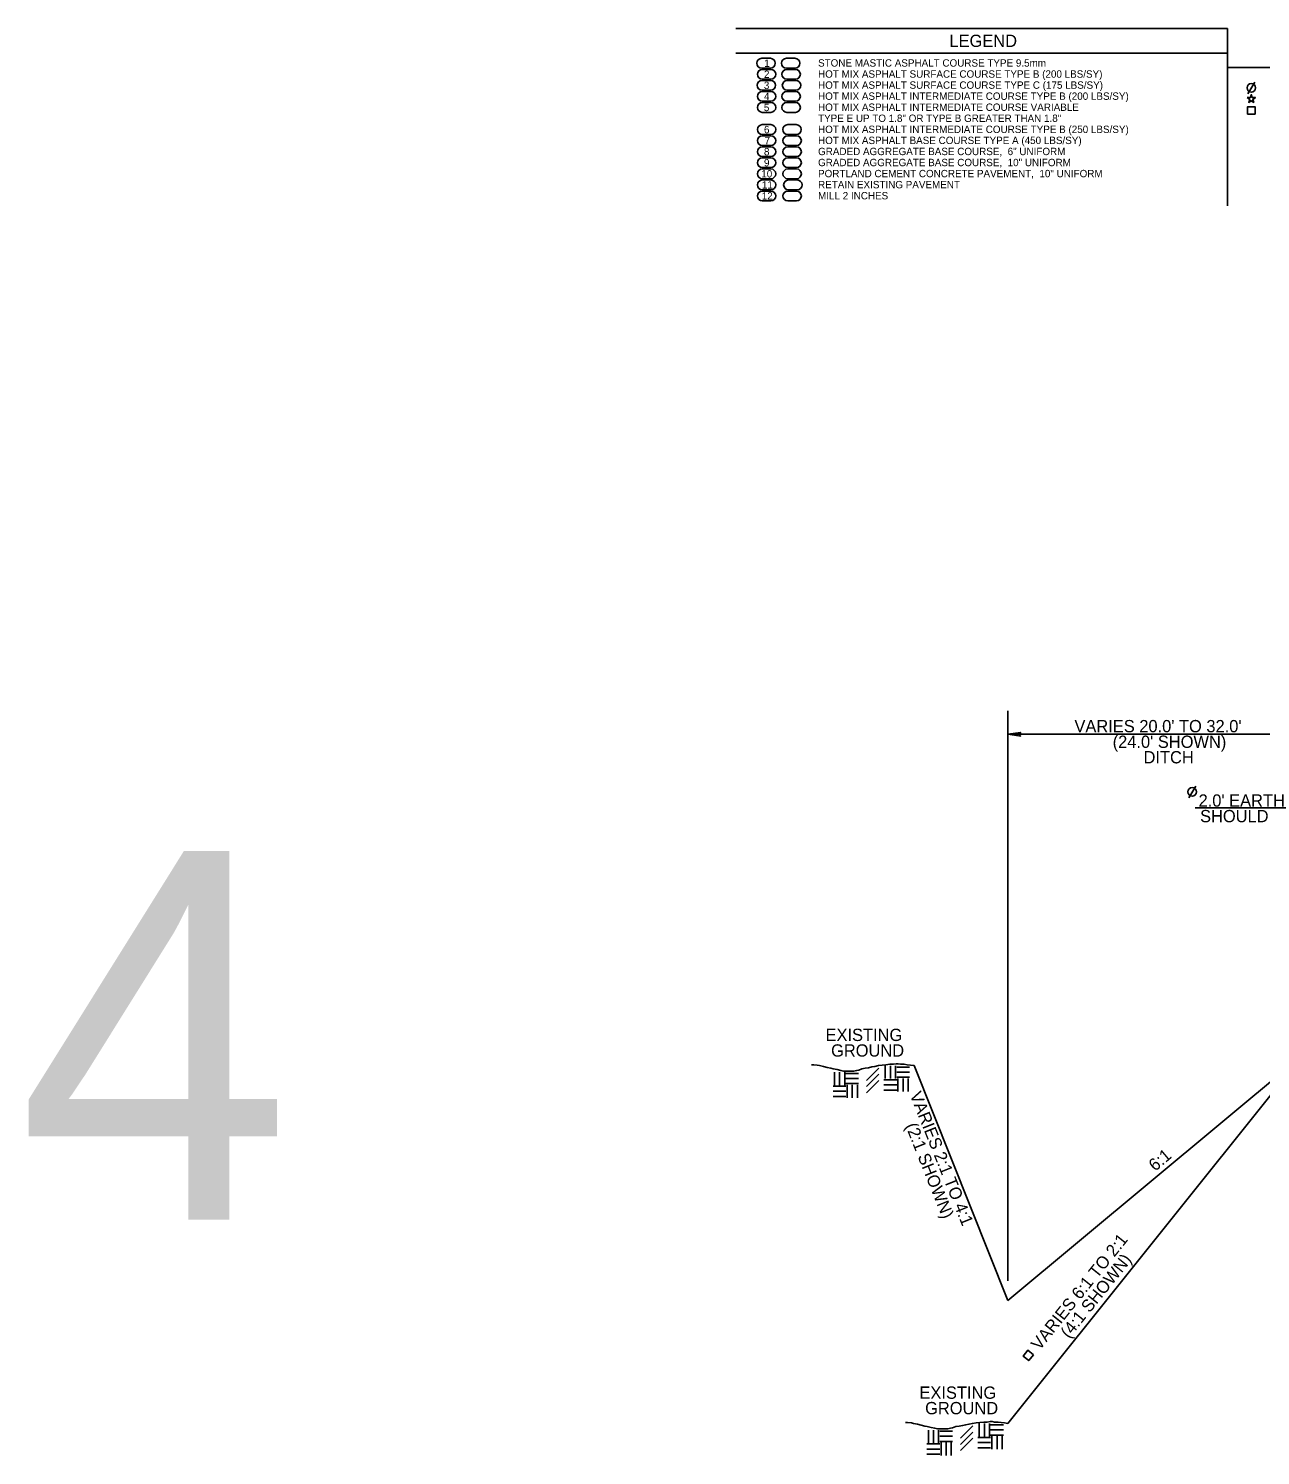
# Model space of a CAD drawing. Extents: x 2003207 to 2014043, y 843846 to 860154.
# Drawn here: x 2013558.2 to 2013658.4, y 844584.3 to 844700.4 of the extents above; entities that cross this region are included whole.
import ezdxf

# ---------------------------------------------------------------- set-up
doc = ezdxf.new("R2010")
doc.units = 0
for name, color, linetype in [('RD_EX_Road', 7, 'Continuous'), ('RD_EX_Road_txCode', 7, 'Continuous'), ('RD_QTY_ConcPave', 7, 'Continuous'), ('RD_QTY_Intermediate', 7, 'Continuous'), ('RD_QTY_Milling', 7, 'Continuous'), ('RD_QTY_PermVeg', 7, 'Continuous'), ('RD_QTY_Surf_Course', 7, 'Continuous'), ('RD_SHT_Bndy', 7, 'Continuous'), ('RD_SHT_TX', 7, 'Continuous'), ('RD_TX_Misc2', 7, 'Continuous'), ('RD_TX_TypSect', 7, 'Continuous'), ('RD_XS_ExGround', 7, 'Continuous')]:
    doc.layers.add(name, color=color, linetype=linetype)

msp = doc.modelspace()

# ---------------------------------------------------------------- linework, layer by layer
at = {"layer": 'RD_EX_Road'}
for p, q in [((2013620.66, 844687.19), (2013619.96, 844687.19)), ((2013620.72, 844688.09), (2013620.02, 844688.09)), ((2013620.02, 844687.29), (2013620.72, 844687.29)), ((2013619.96, 844686.39), (2013620.66, 844686.39))]:
    msp.add_line(p, q, dxfattribs=at)
for centre, start, end in [((2013619.96, 844686.79), 90, 270), ((2013620.02, 844687.69), 90, 270), ((2013620.66, 844686.79), 270, 90), ((2013620.72, 844687.69), 270, 90)]:
    msp.add_arc(centre, 0.4, start, end, dxfattribs=at)
at = {"layer": 'RD_EX_Road_txCode'}
msp.add_line((2013657.38, 844695.11), (2013657.95, 844696.05), dxfattribs=at)
for points in [[(2013657.33, 844694.79), (2013657.59, 844694.79), (2013657.67, 844695.03), (2013657.75, 844694.79), (2013658, 844694.79), (2013657.79, 844694.64), (2013657.87, 844694.4), (2013657.67, 844694.54), (2013657.46, 844694.4), (2013657.54, 844694.64)], [(2013657.37, 844693.45), (2013657.97, 844693.45), (2013657.97, 844694.05), (2013657.37, 844694.05)], [(2013639.94, 844592.49), (2013639.56, 844592.03), (2013639.1, 844592.4), (2013639.48, 844592.87)]]:
    msp.add_lwpolyline(points, close=True, dxfattribs=at)
msp.add_circle((2013657.67, 844695.58), 0.35, dxfattribs=at)
at = {"layer": 'RD_QTY_ConcPave'}
for p, q in [((2013620.66, 844690.79), (2013619.96, 844690.79)), ((2013619.96, 844689.99), (2013620.66, 844689.99)), ((2013620.66, 844689.89), (2013619.96, 844689.89)), ((2013619.96, 844689.09), (2013620.66, 844689.09)), ((2013620.66, 844688.99), (2013619.96, 844688.99)), ((2013619.96, 844688.19), (2013620.66, 844688.19))]:
    msp.add_line(p, q, dxfattribs=at)
for centre, start, end in [((2013619.96, 844690.39), 90, 270), ((2013620.66, 844690.39), 270, 90), ((2013619.96, 844689.49), 90, 270), ((2013620.66, 844689.49), 270, 90), ((2013619.96, 844688.59), 90, 270), ((2013620.66, 844688.59), 270, 90)]:
    msp.add_arc(centre, 0.4, start, end, dxfattribs=at)
at = {"layer": 'RD_QTY_Intermediate'}
for p, q in [((2013620.58, 844695.29), (2013619.88, 844695.29)), ((2013619.88, 844694.49), (2013620.58, 844694.49)), ((2013620.58, 844694.39), (2013619.88, 844694.39)), ((2013619.88, 844693.59), (2013620.58, 844693.59)), ((2013620.65, 844692.59), (2013619.95, 844692.59)), ((2013619.95, 844691.79), (2013620.65, 844691.79)), ((2013620.66, 844691.69), (2013619.96, 844691.69)), ((2013619.96, 844690.89), (2013620.66, 844690.89))]:
    msp.add_line(p, q, dxfattribs=at)
for centre, start, end in [((2013619.88, 844694.89), 90, 270), ((2013620.58, 844694.89), 270, 90), ((2013619.88, 844693.99), 90, 270), ((2013620.58, 844693.99), 270, 90), ((2013619.95, 844692.19), 90, 270), ((2013619.96, 844691.29), 90, 270), ((2013620.65, 844692.19), 270, 90), ((2013620.66, 844691.29), 270, 90)]:
    msp.add_arc(centre, 0.4, start, end, dxfattribs=at)
at = {"layer": 'RD_QTY_Milling'}
for p, q in [((2013620.66, 844687.19), (2013619.96, 844687.19)), ((2013619.96, 844686.39), (2013620.66, 844686.39))]:
    msp.add_line(p, q, dxfattribs=at)
for centre, start, end in [((2013619.96, 844686.79), 90, 270), ((2013620.66, 844686.79), 270, 90)]:
    msp.add_arc(centre, 0.4, start, end, dxfattribs=at)
at = {"layer": 'RD_QTY_PermVeg'}
for p, q in [((2013661.87, 844616.92), (2013637.87, 844596.92)), ((2013661.87, 844616.92), (2013637.87, 844586.92)), ((2013637.87, 844596.92), (2013630.23, 844616.03))]:
    msp.add_line(p, q, dxfattribs=at)
at = {"layer": 'RD_QTY_Surf_Course'}
for p, q in [((2013620.54, 844697.99), (2013619.84, 844697.99)), ((2013619.84, 844697.19), (2013620.54, 844697.19)), ((2013620.58, 844697.09), (2013619.88, 844697.09)), ((2013619.88, 844696.29), (2013620.58, 844696.29)), ((2013620.61, 844696.19), (2013619.91, 844696.19)), ((2013619.91, 844695.39), (2013620.61, 844695.39))]:
    msp.add_line(p, q, dxfattribs=at)
for centre, start, end in [((2013619.84, 844697.59), 90, 270), ((2013620.54, 844697.59), 270, 90), ((2013619.88, 844696.69), 90, 270), ((2013620.58, 844696.69), 270, 90), ((2013619.91, 844695.79), 90, 270), ((2013620.61, 844695.79), 270, 90)]:
    msp.add_arc(centre, 0.4, start, end, dxfattribs=at)
at = {"layer": 'RD_SHT_Bndy'}
for p, q in [((2013655.72, 844700.41), (2013615.72, 844700.41)), ((2013655.72, 844698.41), (2013655.72, 844700.41)), ((2013655.72, 844698.41), (2013615.72, 844698.41)), ((2013655.72, 844685.99), (2013655.72, 844698.41)), ((2013678.75, 844697.24), (2013655.75, 844697.24))]:
    msp.add_line(p, q, dxfattribs=at)
at = {"layer": 'RD_TX_Misc2'}
for p, q in [((2013617.84, 844697.99), (2013618.54, 844697.99)), ((2013619.84, 844697.99), (2013620.54, 844697.99)), ((2013617.84, 844697.19), (2013618.54, 844697.19)), ((2013617.88, 844697.09), (2013618.58, 844697.09)), ((2013617.88, 844696.29), (2013618.58, 844696.29)), ((2013619.84, 844697.19), (2013620.54, 844697.19)), ((2013619.88, 844697.09), (2013620.58, 844697.09)), ((2013619.88, 844696.29), (2013620.58, 844696.29)), ((2013617.87, 844696.19), (2013618.57, 844696.19)), ((2013617.87, 844695.39), (2013618.57, 844695.39)), ((2013617.88, 844695.29), (2013618.58, 844695.29)), ((2013619.88, 844695.29), (2013620.58, 844695.29)), ((2013619.91, 844696.19), (2013620.61, 844696.19)), ((2013619.91, 844695.39), (2013620.61, 844695.39)), ((2013617.88, 844694.49), (2013618.58, 844694.49)), ((2013617.88, 844694.39), (2013618.58, 844694.39)), ((2013619.88, 844694.49), (2013620.58, 844694.49)), ((2013619.88, 844694.39), (2013620.58, 844694.39)), ((2013617.88, 844693.59), (2013618.58, 844693.59)), ((2013619.88, 844693.59), (2013620.58, 844693.59)), ((2013617.88, 844692.59), (2013618.58, 844692.59)), ((2013617.88, 844691.79), (2013618.58, 844691.79)), ((2013617.88, 844691.69), (2013618.58, 844691.69)), ((2013619.95, 844692.59), (2013620.65, 844692.59)), ((2013619.95, 844691.79), (2013620.65, 844691.79)), ((2013619.96, 844691.69), (2013620.66, 844691.69)), ((2013617.88, 844690.89), (2013618.58, 844690.89)), ((2013617.88, 844690.79), (2013618.58, 844690.79)), ((2013619.96, 844690.89), (2013620.66, 844690.89)), ((2013619.96, 844690.79), (2013620.66, 844690.79)), ((2013617.88, 844689.99), (2013618.58, 844689.99)), ((2013617.88, 844689.89), (2013618.58, 844689.89)), ((2013619.96, 844689.99), (2013620.66, 844689.99)), ((2013619.96, 844689.89), (2013620.66, 844689.89)), ((2013617.88, 844689.09), (2013618.58, 844689.09)), ((2013617.88, 844688.99), (2013618.58, 844688.99)), ((2013617.88, 844688.19), (2013618.58, 844688.19)), ((2013619.96, 844689.09), (2013620.66, 844689.09)), ((2013619.96, 844688.99), (2013620.66, 844688.99)), ((2013619.96, 844688.19), (2013620.66, 844688.19)), ((2013617.88, 844688.09), (2013618.58, 844688.09)), ((2013617.88, 844687.29), (2013618.58, 844687.29)), ((2013617.88, 844687.19), (2013618.58, 844687.19)), ((2013619.96, 844687.19), (2013620.66, 844687.19)), ((2013620.02, 844688.09), (2013620.72, 844688.09)), ((2013620.02, 844687.29), (2013620.72, 844687.29)), ((2013617.88, 844686.39), (2013618.58, 844686.39)), ((2013619.96, 844686.39), (2013620.66, 844686.39))]:
    msp.add_line(p, q, dxfattribs=at)
for centre, start, end in [((2013617.84, 844697.59), 90, 270), ((2013618.54, 844697.59), 270, 90), ((2013619.84, 844697.59), 90, 270), ((2013620.54, 844697.59), 270, 90), ((2013617.88, 844696.69), 90, 270), ((2013618.58, 844696.69), 270, 90), ((2013619.88, 844696.69), 90, 270), ((2013620.58, 844696.69), 270, 90), ((2013617.87, 844695.79), 90, 270), ((2013617.88, 844694.89), 90, 270), ((2013618.57, 844695.79), 270, 90), ((2013618.58, 844694.89), 270, 90), ((2013619.88, 844694.89), 90, 270), ((2013619.91, 844695.79), 90, 270), ((2013620.58, 844694.89), 270, 90), ((2013620.61, 844695.79), 270, 90), ((2013617.88, 844693.99), 90, 270), ((2013618.58, 844693.99), 270, 90), ((2013619.88, 844693.99), 90, 270), ((2013620.58, 844693.99), 270, 90), ((2013617.88, 844692.19), 90, 270), ((2013617.88, 844691.29), 90, 270), ((2013618.58, 844692.19), 270, 90), ((2013618.58, 844691.29), 270, 90), ((2013619.95, 844692.19), 90, 270), ((2013619.96, 844691.29), 90, 270), ((2013620.65, 844692.19), 270, 90), ((2013620.66, 844691.29), 270, 90), ((2013617.88, 844690.39), 90, 270), ((2013618.58, 844690.39), 270, 90), ((2013619.96, 844690.39), 90, 270), ((2013620.66, 844690.39), 270, 90), ((2013617.88, 844689.49), 90, 270), ((2013618.58, 844689.49), 270, 90), ((2013619.96, 844689.49), 90, 270), ((2013620.66, 844689.49), 270, 90), ((2013617.88, 844688.59), 90, 270), ((2013618.58, 844688.59), 270, 90), ((2013619.96, 844688.59), 90, 270), ((2013620.66, 844688.59), 270, 90), ((2013617.88, 844687.69), 90, 270), ((2013617.88, 844686.79), 90, 270), ((2013618.58, 844687.69), 270, 90), ((2013618.58, 844686.79), 270, 90), ((2013619.96, 844686.79), 90, 270), ((2013620.02, 844687.69), 90, 270), ((2013620.66, 844686.79), 270, 90), ((2013620.72, 844687.69), 270, 90)]:
    msp.add_arc(centre, 0.4, start, end, dxfattribs=at)
at = {"layer": 'RD_TX_TypSect'}
for p, q in [((2013637.87, 844598.52), (2013637.87, 844644.89)), ((2013637.87, 844642.99), (2013661.87, 844642.99)), ((2013652.58, 844637.83), (2013653.15, 844638.77)), ((2013653.09, 844636.99), (2013661.87, 844636.99))]:
    msp.add_line(p, q, dxfattribs=at)
msp.add_lwpolyline([(2013637.87, 844642.99), (2013638.91, 844642.84), (2013638.75, 844642.99), (2013638.91, 844643.14)], close=True, dxfattribs=at)
msp.add_circle((2013652.86, 844638.3), 0.35, dxfattribs=at)
at = {"layer": 'RD_XS_ExGround'}
for p, q in [((2013623.75, 844615.49), (2013623.75, 844614.45)), ((2013624.17, 844615.49), (2013624.17, 844614.45)), ((2013624.59, 844615.49), (2013624.59, 844614.45)), ((2013624.68, 844615.4), (2013625.72, 844615.4)), ((2013626.37, 844614.82), (2013627.37, 844615.82)), ((2013626.37, 844614.32), (2013627.37, 844615.32)), ((2013627.89, 844616.01), (2013627.89, 844614.97)), ((2013628.31, 844616.01), (2013628.31, 844614.97)), ((2013628.72, 844616.01), (2013628.72, 844614.97)), ((2013628.82, 844615.91), (2013629.86, 844615.91)), ((2013628.82, 844615.5), (2013629.86, 844615.5)), ((2013628.82, 844615.08), (2013629.86, 844615.08)), ((2013623.64, 844614.35), (2013624.68, 844614.35)), ((2013623.64, 844613.94), (2013624.68, 844613.94)), ((2013624.68, 844614.98), (2013625.72, 844614.98)), ((2013624.68, 844614.56), (2013625.72, 844614.56)), ((2013624.79, 844614.46), (2013624.79, 844613.42)), ((2013625.2, 844614.46), (2013625.2, 844613.42)), ((2013625.62, 844614.46), (2013625.62, 844613.42)), ((2013626.37, 844613.82), (2013627.37, 844614.82)), ((2013627.78, 844614.87), (2013628.82, 844614.87)), ((2013627.78, 844614.46), (2013628.82, 844614.46)), ((2013627.78, 844614.04), (2013628.82, 844614.04)), ((2013628.92, 844614.98), (2013628.92, 844613.93)), ((2013629.34, 844614.98), (2013629.34, 844613.93)), ((2013629.76, 844614.98), (2013629.76, 844613.93)), ((2013623.64, 844613.52), (2013624.68, 844613.52)), ((2013631.4, 844586.38), (2013631.4, 844585.34)), ((2013631.81, 844586.38), (2013631.81, 844585.34)), ((2013632.23, 844586.38), (2013632.23, 844585.34)), ((2013632.33, 844586.29), (2013633.37, 844586.29)), ((2013634.01, 844585.71), (2013635.01, 844586.71)), ((2013634.01, 844585.21), (2013635.01, 844586.21)), ((2013635.53, 844586.9), (2013635.53, 844585.86)), ((2013635.95, 844586.9), (2013635.95, 844585.86)), ((2013636.37, 844586.9), (2013636.37, 844585.86)), ((2013636.46, 844586.81), (2013637.5, 844586.81)), ((2013636.46, 844586.39), (2013637.5, 844586.39)), ((2013631.28, 844585.25), (2013632.33, 844585.25)), ((2013631.28, 844584.83), (2013632.33, 844584.83)), ((2013632.33, 844585.87), (2013633.37, 844585.87)), ((2013632.33, 844585.45), (2013633.37, 844585.45)), ((2013632.43, 844585.35), (2013632.43, 844584.31)), ((2013632.85, 844585.35), (2013632.85, 844584.31)), ((2013633.26, 844585.35), (2013633.26, 844584.31)), ((2013634.01, 844584.71), (2013635.01, 844585.71)), ((2013635.42, 844585.76), (2013636.46, 844585.76)), ((2013635.42, 844585.35), (2013636.46, 844585.35)), ((2013635.42, 844584.93), (2013636.46, 844584.93)), ((2013636.46, 844585.97), (2013637.5, 844585.97)), ((2013636.57, 844585.87), (2013636.57, 844584.83)), ((2013636.98, 844585.87), (2013636.98, 844584.83)), ((2013637.4, 844585.87), (2013637.4, 844584.83)), ((2013631.28, 844584.41), (2013632.33, 844584.41))]:
    msp.add_line(p, q, dxfattribs=at)
for points in [[(2013621.89, 844616.1), (2013622.07, 844616.1), (2013622.36, 844616.06), (2013622.55, 844616.03), (2013622.87, 844615.95), (2013623.17, 844615.88), (2013623.46, 844615.81), (2013623.64, 844615.77), (2013623.97, 844615.7), (2013624.27, 844615.62), (2013624.49, 844615.59), (2013624.67, 844615.59), (2013624.89, 844615.59), (2013625.11, 844615.59), (2013625.33, 844615.59), (2013625.55, 844615.62), (2013625.73, 844615.66), (2013625.99, 844615.77), (2013626.24, 844615.81), (2013626.53, 844615.84), (2013626.79, 844615.92), (2013627.05, 844615.95), (2013627.34, 844616.03), (2013627.63, 844616.06), (2013627.93, 844616.1), (2013628.26, 844616.14), (2013628.55, 844616.14), (2013628.77, 844616.17), (2013628.95, 844616.17), (2013629.13, 844616.14), (2013629.43, 844616.14), (2013629.68, 844616.1), (2013629.94, 844616.06), (2013630.23, 844616.03)], [(2013629.54, 844586.99), (2013629.71, 844586.99), (2013630.01, 844586.96), (2013630.19, 844586.92), (2013630.52, 844586.85), (2013630.81, 844586.77), (2013631.1, 844586.7), (2013631.29, 844586.66), (2013631.62, 844586.59), (2013631.91, 844586.52), (2013632.13, 844586.48), (2013632.31, 844586.48), (2013632.53, 844586.48), (2013632.75, 844586.48), (2013632.97, 844586.48), (2013633.19, 844586.52), (2013633.37, 844586.55), (2013633.63, 844586.66), (2013633.89, 844586.7), (2013634.18, 844586.74), (2013634.43, 844586.81), (2013634.69, 844586.85), (2013634.98, 844586.92), (2013635.28, 844586.96), (2013635.57, 844586.99), (2013635.9, 844587.03), (2013636.19, 844587.03), (2013636.41, 844587.07), (2013636.59, 844587.07), (2013636.78, 844587.03), (2013637.07, 844587.03), (2013637.33, 844586.99), (2013637.58, 844586.96), (2013637.87, 844586.92)]]:
    msp.add_lwpolyline(points, dxfattribs=at)

# ---------------------------------------------------------------- texts
at = {"layer": 'RD_EX_Road_txCode'}
for s, height, p in [('LEGEND', 1, (2013633.11, 844698.91)), ('STONE MASTIC ASPHALT COURSE TYPE 9.5mm', 0.6, (2013622.42, 844697.31)), ('HOT MIX ASPHALT SURFACE COURSE TYPE B (200 LBS/SY)', 0.6, (2013622.42, 844696.41)), ('HOT MIX ASPHALT SURFACE COURSE TYPE C (175 LBS/SY)', 0.6, (2013622.42, 844695.51)), ('HOT MIX ASPHALT INTERMEDIATE COURSE TYPE B (200 LBS/SY)', 0.6, (2013622.42, 844694.61)), ('HOT MIX ASPHALT INTERMEDIATE COURSE VARIABLE ', 0.6, (2013622.42, 844693.71)), ('TYPE E UP TO 1.8" OR TYPE B GREATER THAN 1.8"', 0.6, (2013622.42, 844692.81)), ('HOT MIX ASPHALT INTERMEDIATE COURSE TYPE B (250 LBS/SY)', 0.6, (2013622.42, 844691.91)), ('HOT MIX ASPHALT BASE COURSE TYPE A (450 LBS/SY)', 0.6, (2013622.42, 844691.01)), ('GRADED AGGREGATE BASE COURSE,  6" UNIFORM', 0.6, (2013622.42, 844690.11)), ('GRADED AGGREGATE BASE COURSE,  10" UNIFORM', 0.6, (2013622.42, 844689.21)), ('PORTLAND CEMENT CONCRETE PAVEMENT,  10" UNIFORM', 0.6, (2013622.42, 844688.31)), ('RETAIN EXISTING PAVEMENT', 0.6, (2013622.42, 844687.41)), ('MILL 2 INCHES', 0.6, (2013622.42, 844686.51))]:
    msp.add_text(s, height=height, dxfattribs=at).set_placement(p)
at = {"layer": 'RD_SHT_TX'}
msp.add_text('4', height=30, dxfattribs=at).set_placement((2013557.27, 844603.49))
at = {"layer": 'RD_TX_Misc2'}
for s, p in [('1', (2013618.04, 844697.29)), ('2', (2013618.02, 844696.39)), ('3', (2013618.01, 844695.49)), ('4', (2013618.02, 844694.59)), ('5', (2013618.01, 844693.69)), ('6', (2013618.02, 844691.89)), ('8', (2013618.02, 844690.09)), ('7 ', (2013618.07, 844690.99)), ('9', (2013618.02, 844689.19)), ('10', (2013617.8, 844688.29)), ('12', (2013617.84, 844686.49)), ('11', (2013617.85, 844687.39))]:
    msp.add_text(s, height=0.6, dxfattribs=at).set_placement(p)
at = {"layer": 'RD_TX_TypSect'}
for s, p in [("VARIES 20.0' TO 32.0'", (2013643.28, 844643.15)), ("(24.0' SHOWN)", (2013646.39, 844641.88)), ('DITCH', (2013648.9, 844640.62)), ("2.0' EARTH", (2013653.38, 844637.1)), ('SHOULDER', (2013653.5, 844635.83)), ('EXISTING', (2013623.03, 844618.03)), ('GROUND', (2013623.48, 844616.76)), ('EXISTING', (2013630.67, 844588.92)), ('GROUND', (2013631.13, 844587.66))]:
    msp.add_text(s, height=1, dxfattribs=at).set_placement(p)
for s, rotation, p in [('VARIES 2:1 TO 4:1', 291.8014, (2013629.86, 844613.67)), ('(2:1 SHOWN)', 291.8014, (2013629.51, 844611.14)), ('6:1', 40.2316, (2013649.84, 844607.38)), ('VARIES 6:1 TO 2:1', 51.3402, (2013640.44, 844592.8)), ('(4:1 SHOWN)', 51.3402, (2013642.84, 844593.77))]:
    msp.add_text(s, height=1, rotation=rotation, dxfattribs=at).set_placement(p)

doc.saveas('drawing.dxf')
